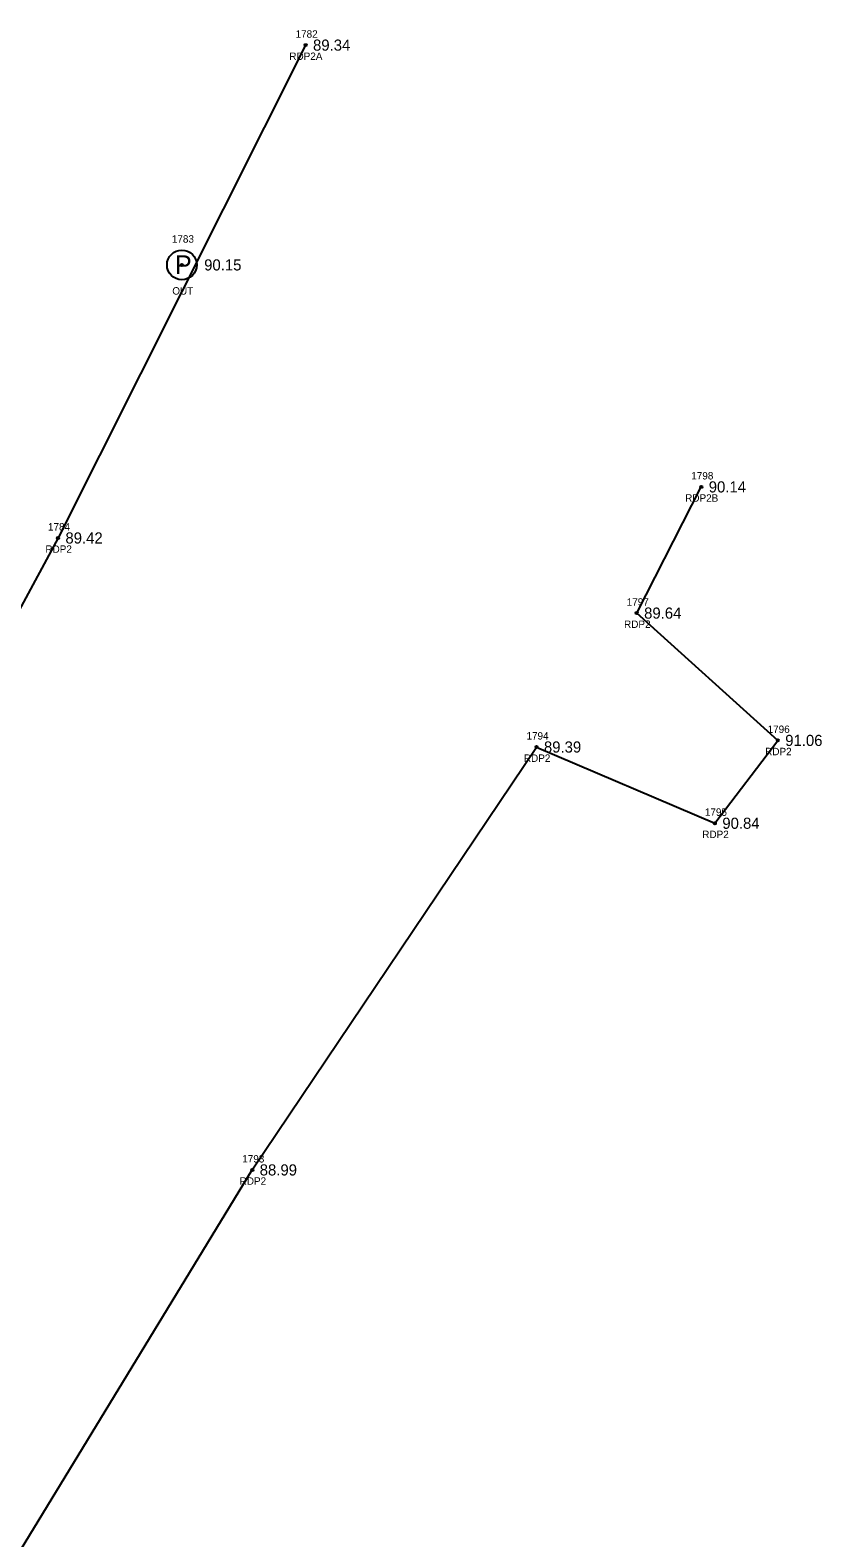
# Model space of a CAD drawing. Extents: x 2529517 to 2532038, y 935000 to 936944.
# Drawn here: x 2531876.1 to 2531982.7, y 936351.6 to 936554.7 of the extents above; entities that cross this region are included whole.
import ezdxf

# ---------------------------------------------------------------- set-up
doc = ezdxf.new("R2010")
doc.units = 0
for name, color, linetype in [('RD_EX_BldgApp', 7, 'Continuous'), ('RD_EX_BldgApp_txCode', 7, 'Continuous'), ('RD_EX_DR_ErosCtrl', 7, 'Continuous'), ('RD_EX_DR_ErosCtrl_txCode', 7, 'Continuous'), ('RD_EX_TX_BldgApp_ELEV', 7, 'Continuous'), ('RD_EX_TX_DR_ErosCtrl_ELEV', 7, 'Continuous'), ('RD_SMD_Locator', 7, 'Continuous')]:
    doc.layers.add(name, color=color, linetype=linetype)

msp = doc.modelspace()

# ---------------------------------------------------------------- linework, layer by layer
at = {"layer": 'RD_EX_BldgApp'}
for radius in [2, 0.15]:
    msp.add_circle((2531896.57, 936523.04), radius, dxfattribs=at)
at = {"layer": 'RD_EX_DR_ErosCtrl'}
for points in [[(2531913.23, 936552.65), (2531879.89, 936486.26), (2531843.11, 936418.02), (2531806.11, 936350.73), (2531797.19, 936330.95), (2531817.13, 936316.37), (2531822.13, 936313.28)], [(2531826.03, 936317.37), (2531842.02, 936350.64), (2531872.46, 936345.98), (2531906.05, 936401.13), (2531944.32, 936458.1), (2531968.34, 936447.83), (2531976.81, 936458.99), (2531957.81, 936476.14), (2531966.51, 936493.14)]]:
    msp.add_lwpolyline(points, dxfattribs=at)
at = {"layer": 'RD_SMD_Locator'}
for centre in [(2531913.23, 936552.65), (2531966.51, 936493.14), (2531879.89, 936486.26), (2531957.81, 936476.14), (2531944.32, 936458.1), (2531976.81, 936458.99), (2531968.34, 936447.83), (2531906.05, 936401.13)]:
    msp.add_circle(centre, 0.15, dxfattribs=at)

# ---------------------------------------------------------------- texts
at = {"layer": 'RD_EX_BldgApp'}
msp.add_text('P', height=2.5, dxfattribs=at).set_placement((2531895.66, 936521.82))
at = {"layer": 'RD_EX_BldgApp_txCode'}
for s, p in [('1783', (2531895.22, 936526.04)), ('OUT', (2531895.28, 936519.04))]:
    msp.add_text(s, height=1, dxfattribs=at).set_placement(p)
at = {"layer": 'RD_EX_DR_ErosCtrl_txCode'}
for s, p in [('1782', (2531911.88, 936553.65)), ('RDP2A', (2531911.04, 936550.65)), ('1798', (2531965.16, 936494.14)), ('RDP2B', (2531964.34, 936491.14)), ('1784', (2531878.54, 936487.26)), ('RDP2', (2531878.19, 936484.26)), ('1797', (2531956.47, 936477.14)), ('RDP2', (2531956.11, 936474.14)), ('1794', (2531942.97, 936459.1)), ('1796', (2531975.44, 936459.99)), ('RDP2', (2531975.11, 936456.99)), ('RDP2', (2531942.62, 936456.1)), ('1795', (2531966.99, 936448.83)), ('RDP2', (2531966.64, 936445.83)), ('1793', (2531904.7, 936402.13)), ('RDP2', (2531904.35, 936399.13))]:
    msp.add_text(s, height=1, dxfattribs=at).set_placement(p)
at = {"layer": 'RD_EX_TX_BldgApp_ELEV'}
msp.add_text('90.15', height=1.5, dxfattribs=at).set_placement((2531899.57, 936522.29))
at = {"layer": 'RD_EX_TX_DR_ErosCtrl_ELEV'}
for s, p in [('89.34', (2531914.23, 936551.9)), ('90.14', (2531967.51, 936492.39)), ('89.42', (2531880.89, 936485.51)), ('89.64', (2531958.81, 936475.39)), ('91.06', (2531977.81, 936458.24)), ('89.39', (2531945.32, 936457.35)), ('90.84', (2531969.34, 936447.08)), ('88.99', (2531907.05, 936400.38))]:
    msp.add_text(s, height=1.5, dxfattribs=at).set_placement(p)

doc.saveas('drawing.dxf')
